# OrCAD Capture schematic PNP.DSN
size A
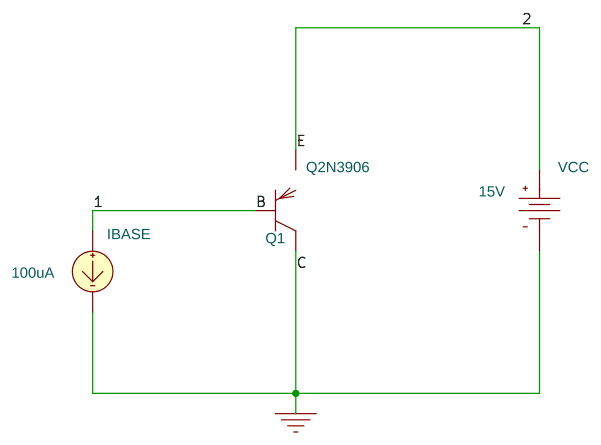
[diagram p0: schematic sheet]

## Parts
IBASE  IDC
Q1  Q2N3906  [TO92]
VCC  VDC

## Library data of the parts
IBASE = IDC: DC: 100uA
Q1 = Q2N3906
VCC = VDC: DC: 15V

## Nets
0: IBASE.2(-) Q1.3(c) VCC.1(-)
1: IBASE.1(+) Q1.2(b)
2: Q1.1(e) VCC.0(+)
